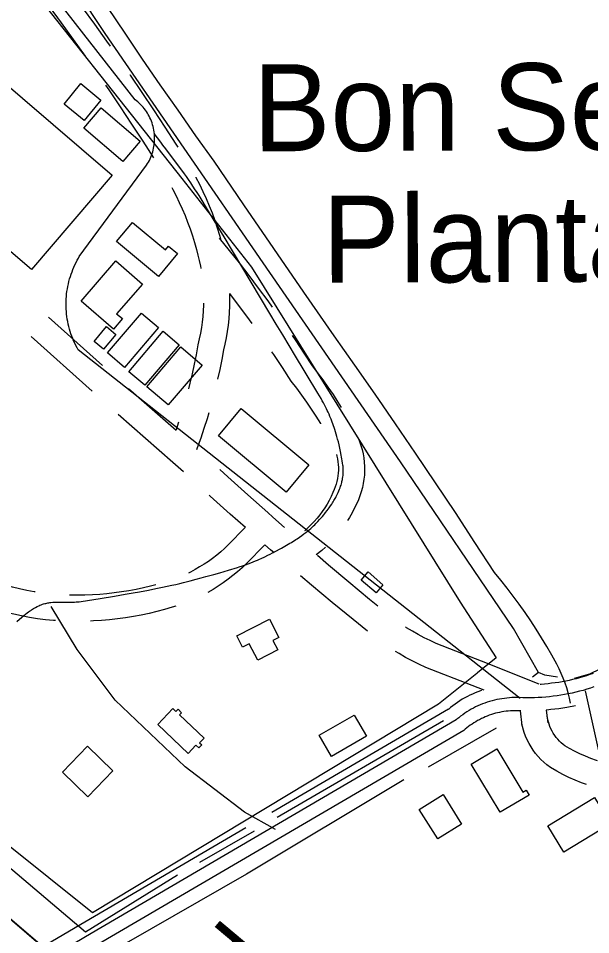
# Model space of a CAD drawing. Extents: x 3424494 to 3462436, y 522220 to 547718.
# Drawn here: x 3435143 to 3435801, y 542993 to 544046 of the extents above; entities that cross this region are included whole.
import ezdxf

# ---------------------------------------------------------------- set-up
doc = ezdxf.new("R2010")
doc.units = 0
for name, color, linetype in [('V-BLDG-IDEN', 7, 'Continuous'), ('V-BLDG-OTLN', 7, 'Continuous'), ('V-DTCH-CNTR', 7, 'Continuous'), ('V-RAIL-IDEN', 7, 'Continuous'), ('V-RAIL-TRAK', 7, 'Continuous'), ('V-ROAD-CNTR', 7, 'Continuous'), ('V-SITE-OTLN', 7, 'Continuous'), ('V-TOPO-SHOR', 7, 'Continuous')]:
    doc.layers.add(name, color=color, linetype=linetype)

msp = doc.modelspace()

# ---------------------------------------------------------------- linework, layer by layer
at = {"layer": 'V-BLDG-OTLN'}
for points in [[(3435079.4, 544012.7), (3435250.7, 543866.1), (3435157.9, 543757.6), (3434986.6, 543904.2)], [(3435195.4, 543947.7), (3435214.7, 543971.3), (3435237.8, 543952.4), (3435218.5, 543928.8)], [(3435238.1, 543943.5), (3435282.9, 543905.3), (3435262.9, 543881.8), (3435218, 543920)], [(3435273.9, 543811.8), (3435311.9, 543780.4), (3435315.4, 543784.7), (3435325.8, 543776.1), (3435304.1, 543749.8), (3435255.7, 543789.8)], [(3435254.9, 543767.5), (3435285.4, 543741), (3435255.8, 543706.9), (3435262.4, 543701.2), (3435252, 543689.2), (3435214.9, 543721.4)], [(3435245.4, 543661.8), (3435284.4, 543707.4), (3435303.8, 543690.9), (3435264.8, 543645.2)], [(3435255, 543682.9), (3435240.7, 543666), (3435230, 543675), (3435244.3, 543692)], [(3435270, 543640.1), (3435309.4, 543686.7), (3435327.7, 543671.2), (3435288.3, 543624.6)], [(3435290.4, 543623), (3435329.6, 543668.8), (3435354.2, 543647.8), (3435315, 543602)], [(3435398.9, 543598), (3435476.6, 543533.3), (3435450.5, 543501.9), (3435372.8, 543566.6)], [(3435544.8, 543410.1), (3435561.9, 543395.3), (3435554, 543386.1), (3435536.8, 543400.8)], [(3435393.9, 543336.6), (3435431.4, 543355.9), (3435442.2, 543334.9), (3435435.3, 543331.4), (3435440.9, 543320.4), (3435418, 543308.6), (3435408.3, 543327.5), (3435400.6, 543323.6)], [(3435328.2, 543245.8), (3435356.3, 543219.2), (3435351.2, 543213.8), (3435353.8, 543211.4), (3435350.4, 543207.9), (3435347, 543211.1), (3435338, 543201.6), (3435303.1, 543234.6), (3435320.5, 543253), (3435324, 543249.8), (3435326.4, 543252.3), (3435330.5, 543248.3)], [(3435542.8, 543221.3), (3435502.6, 543198), (3435488.5, 543222.3), (3435528.8, 543245.6)], [(3435193.6, 543179.8), (3435222.4, 543209.7), (3435251.5, 543181.6), (3435222.7, 543151.8)], [(3435692.9, 543206.6), (3435722.5, 543157.1), (3435726.4, 543159.4), (3435729.8, 543153.7), (3435696.5, 543133.8), (3435663.4, 543189)], [(3435631, 543154.1), (3435652.1, 543120.3), (3435624.9, 543103.3), (3435603.7, 543137.1)], [(3435751.5, 543118.3), (3435805, 543150.8), (3435823.4, 543120.6), (3435769.9, 543088)]]:
    msp.add_lwpolyline(points, close=True, dxfattribs=at)
at = {"layer": 'V-DTCH-CNTR'}
for points in [[(3435761.7, 543304.1), (3435756.1, 543314.3), (3435750.2, 543324.4), (3435744.3, 543334.3), (3435738.1, 543344.2), (3435731.7, 543353.9), (3435725.2, 543363.5), (3435718.5, 543373), (3435711.6, 543382.3), (3435704.6, 543391.6), (3435697.4, 543400.7), (3435690, 543409.6), (3435667.6, 543444.1), (3435645.1, 543478.4), (3435622.3, 543512.5), (3435599.4, 543546.6), (3435576.2, 543580.5), (3435552.9, 543614.3), (3435529.4, 543647.9), (3435505.7, 543681.5), (3435471, 543731.5), (3435436.4, 543781.7), (3435402, 543831.9), (3435367.8, 543882.3), (3435347, 543911.4), (3435326.4, 543940.7), (3435306, 543970.1), (3435285.7, 543999.5), (3435265.6, 544029.2), (3435245.7, 544058.9)], [(3435777.6, 543259.4), (3435776.3, 543265.2), (3435774.8, 543271), (3435773.1, 543276.7), (3435771.2, 543282.3), (3435769.1, 543287.9), (3435766.8, 543293.4), (3435764.3, 543298.8), (3435761.7, 543304.1)]]:
    msp.add_lwpolyline(points, dxfattribs=at)
at = {"layer": 'V-RAIL-TRAK'}
msp.add_lwpolyline([(3435190.4, 542962.1), (3435035.7, 543094.7), (3434892.9, 543218.6), (3434779.9, 543315.6), (3434627.7, 543445.6), (3434493.1, 543559.8), (3434400.9, 543640.1), (3434291.5, 543733.7), (3434167.1, 543840.9), (3434043.4, 543946.1), (3433898.6, 544070.1), (3433740.4, 544206.3), (3433526, 544390.6), (3433337.1, 544551.9)], dxfattribs=at)
at = {"layer": 'V-ROAD-CNTR'}
for p, q in [((3435352.1, 543761.8), (3435352.6, 543758.7)), ((3435239.7, 543647.2), (3435177.4, 543702.9)), ((3435227.6, 543617.8), (3435157.4, 543680.6)), ((3435721.8, 543233.5), (3435719.9, 543250.5)), ((3435751.6, 543236.8), (3435750, 543251.3))]:
    msp.add_line(p, q, dxfattribs=at)
for points in [[(3432086.3, 545626.6), (3433017.5, 544826.1), (3436584, 541768.3), (3439656.2, 539130.4), (3440791.3, 538157.4)], [(3435189.1, 544095.2), (3435202.1, 544078), (3435216.3, 544058.9), (3435230.3, 544039.6), (3435244.2, 544020.2), (3435248.2, 544014.5)], [(3435277.2, 543952.8), (3435172.7, 544086.5)], [(3435161.1, 544083), (3435163.5, 544079.3), (3435178.1, 544060.1), (3435192.1, 544041.1), (3435206, 544022.1), (3435219.7, 544002.9), (3435220.1, 544002.3)], [(3435271, 543981.7), (3435271.5, 543981), (3435284.8, 543961.3), (3435298, 543941.4), (3435311, 543921.4), (3435323.7, 543901.6), (3435326, 543898.2)], [(3435243, 543969.5), (3435246.7, 543964.1), (3435259.9, 543944.6), (3435272.9, 543924.9), (3435285.8, 543905.2), (3435298, 543886)], [(3435290.2, 543877.6), (3435291.4, 543879.4), (3435292.4, 543881.2), (3435293.4, 543883.1), (3435294.3, 543885), (3435295.2, 543886.9), (3435296, 543888.9), (3435296.7, 543890.9), (3435297.3, 543892.9), (3435297.8, 543894.9), (3435298.3, 543897), (3435298.7, 543899.1), (3435299, 543901.1), (3435299.2, 543903.2), (3435299.4, 543905.3), (3435299.4, 543907.5), (3435299.4, 543909.6), (3435299.3, 543911.7), (3435299.2, 543913.8), (3435298.9, 543915.9), (3435298.6, 543918), (3435298.2, 543920), (3435297.7, 543922.1), (3435297.1, 543924.1), (3435296.5, 543926.1), (3435295.8, 543928.1), (3435295, 543930.1), (3435294.1, 543932), (3435293.2, 543933.9), (3435292.2, 543935.7), (3435291.1, 543937.5), (3435290, 543939.3), (3435288.8, 543941), (3435287.5, 543942.7), (3435286.2, 543944.4), (3435284.8, 543945.9), (3435283.3, 543947.5), (3435281.8, 543948.9), (3435280.2, 543950.3), (3435278.6, 543951.7), (3435277.2, 543952.8)], [(3435306.5, 543904), (3435302.8, 543909), (3435299.1, 543914.1)], [(3435503.9, 543489.4), (3435504.7, 543490.8), (3435505.5, 543492.1), (3435506.3, 543493.4), (3435507, 543494.6), (3435507.6, 543495.8), (3435508.2, 543496.9), (3435509.4, 543499.2), (3435510.4, 543501.3), (3435511.2, 543503.3), (3435512, 543505.1), (3435512.7, 543506.9), (3435513.2, 543508.5), (3435513.7, 543510), (3435514.1, 543511.5), (3435514.5, 543512.8), (3435514.8, 543514.1), (3435515.1, 543515.3), (3435515.3, 543516.4), (3435515.5, 543517.4), (3435515.8, 543519.4), (3435516, 543521.1), (3435516.1, 543522.6), (3435516.2, 543523.9), (3435516.3, 543525), (3435516.3, 543526), (3435516.3, 543527.7), (3435516.2, 543529), (3435516.2, 543530), (3435516, 543531.5), (3435515.8, 543532.9), (3435515.5, 543535.3), (3435515.1, 543537.7), (3435514.8, 543539.9), (3435514.4, 543542.1), (3435514, 543544.3), (3435513.2, 543548.5), (3435512.4, 543552.4), (3435511.5, 543556.1), (3435510.7, 543559.5), (3435509.8, 543562.8), (3435509, 543565.8), (3435508.2, 543568.6), (3435507.4, 543571.3), (3435506.6, 543573.7), (3435505.8, 543576.1), (3435505.1, 543578.2), (3435504.3, 543580.3), (3435503.6, 543582.2), (3435502.3, 543585.7), (3435501, 543588.7), (3435499.9, 543591.4), (3435498.8, 543593.7), (3435497.9, 543595.7), (3435497.1, 543597.5), (3435495.6, 543600.5), (3435494.4, 543602.8), (3435493.5, 543604.4), (3435492.1, 543606.9), (3435490.7, 543609.4), (3435487, 543615.6), (3435483.6, 543621.4), (3435477.1, 543632.2), (3435471.5, 543641.6), (3435461.5, 543658), (3435446.7, 543682.5), (3435439.2, 543694.8), (3435431.9, 543707.2), (3435410.4, 543743.2), (3435388.9, 543779.2), (3435379.4, 543795.1), (3435372.2, 543807), (3435361.4, 543824.8), (3435350.5, 543842.6), (3435349.1, 543844.9), (3435347.6, 543847.2), (3435346.2, 543849.4), (3435343.5, 543853.6), (3435340.9, 543857.4), (3435338.4, 543861), (3435336, 543864.4), (3435333.7, 543867.5), (3435329.4, 543873.4), (3435325.7, 543878.5), (3435312.3, 543896.2), (3435308.9, 543900.7), (3435306.5, 543904)], [(3435212.9, 543772.5), (3435290.2, 543877.6)], [(3435346.7, 543864), (3435346.9, 543863.6), (3435351, 543855.6), (3435355, 543847.5), (3435358.7, 543839.3), (3435362.2, 543831), (3435365.5, 543822.7), (3435368.6, 543814.2), (3435371.4, 543805.7), (3435374.1, 543797.1), (3435375.7, 543791.6)], [(3435319.1, 543852), (3435320.4, 543849.5), (3435324.2, 543842.2), (3435327.8, 543834.8), (3435331.2, 543827.3), (3435334.4, 543819.7), (3435337.4, 543812), (3435340.3, 543804.3), (3435342.9, 543796.5), (3435345.3, 543788.6), (3435347.6, 543780.6), (3435349.3, 543774.2), (3435350.8, 543767.9), (3435352.2, 543761.4)], [(3435373.8, 543793.9), (3435385.2, 543779.6), (3435396.5, 543765.3), (3435407.6, 543750.8), (3435418.6, 543736.3), (3435429.4, 543721.6), (3435434.5, 543714.5)], [(3435211.7, 543665.2), (3435210.3, 543667.7), (3435208.9, 543670.3), (3435207.6, 543672.9), (3435206.4, 543675.6), (3435205.3, 543678.3), (3435204.3, 543681), (3435203.3, 543683.7), (3435202.4, 543686.5), (3435201.6, 543689.3), (3435200.8, 543692.1), (3435200.2, 543695), (3435199.6, 543697.8), (3435199.1, 543700.7), (3435198.6, 543703.6), (3435198.3, 543706.5), (3435198, 543709.4), (3435197.8, 543712.3), (3435197.7, 543715.2), (3435197.7, 543718.1), (3435197.7, 543721), (3435197.9, 543723.9), (3435198.1, 543726.8), (3435198.3, 543729.7), (3435198.7, 543732.6), (3435199.2, 543735.5), (3435199.7, 543738.3), (3435200.3, 543741.2), (3435201, 543744), (3435201.7, 543746.8), (3435202.6, 543749.6), (3435203.5, 543752.4), (3435204.5, 543755.1), (3435205.5, 543757.8), (3435206.7, 543760.5), (3435207.9, 543763.2), (3435209.1, 543765.8), (3435210.5, 543768.4), (3435211.9, 543770.9), (3435212.9, 543772.5)], [(3435385.6, 543730.2), (3435385.7, 543723.1), (3435385.6, 543715.7), (3435385.3, 543708.3), (3435384.7, 543700.9), (3435383.9, 543693.6), (3435382.9, 543686.3), (3435381.6, 543679), (3435380.1, 543671.7), (3435378.5, 543665.2), (3435376.6, 543654.2), (3435374.3, 543642.7), (3435371.8, 543631.5)], [(3435385.6, 543730.2), (3435394.5, 543718.4), (3435405.1, 543704), (3435411, 543695.8)], [(3435355.7, 543718.9), (3435355.6, 543716.6), (3435355.3, 543710.2), (3435354.8, 543703.7), (3435354.1, 543697.3), (3435353.2, 543690.9), (3435352.1, 543684.6), (3435350.8, 543678.2), (3435349.2, 543671.3), (3435347.1, 543659.8), (3435344.9, 543648.8), (3435342.5, 543637.9), (3435340, 543627.1), (3435338.3, 543620.6)], [(3435457.4, 543681.7), (3435460.8, 543676.8), (3435470.9, 543661.7), (3435480.5, 543647), (3435486.4, 543639.4), (3435492.6, 543631), (3435498.6, 543622.5), (3435504.5, 543613.9), (3435510.1, 543605.2), (3435513.9, 543599.2)], [(3435719.7, 543264.8), (3435211.7, 543665.2)], [(3435433.9, 543663), (3435435.9, 543660), (3435445.9, 543645.1), (3435456, 543629.5), (3435462.5, 543621.2), (3435468.3, 543613.4), (3435474, 543605.4), (3435479.5, 543597.3), (3435484.8, 543589.1), (3435490, 543580.8), (3435490.2, 543580.4)], [(3435324.1, 543572.7), (3435272, 543618.4), (3435269.6, 543620.6)], [(3435332.6, 543525.3), (3435320.5, 543535.9), (3435257.5, 543591.2)], [(3435361.7, 543592.8), (3435359.7, 543586), (3435356.2, 543574.9), (3435352.5, 543563.8), (3435348.5, 543552.7), (3435347.7, 543550.6)], [(3435327, 543582.2), (3435324.1, 543573.6), (3435323.9, 543572.9)], [(3435533.3, 543564.3), (3435535, 543560), (3435536.6, 543555.4), (3435537.9, 543550.7), (3435539, 543545.9), (3435539.8, 543541.1), (3435540.4, 543536.2), (3435540.7, 543531.3), (3435540.7, 543526.4), (3435540.5, 543521.5), (3435540, 543516.6), (3435539.2, 543511.8), (3435538.2, 543507), (3435536.9, 543502.3), (3435535.4, 543497.6), (3435533.6, 543493.1), (3435531.7, 543488.9), (3435529.2, 543483.6), (3435526.4, 543478.1), (3435523.4, 543472.7), (3435521.3, 543469.3)], [(3435508.4, 543544.9), (3435508.8, 543543.3), (3435509.6, 543540.1), (3435510.1, 543536.8), (3435510.5, 543533.6), (3435510.7, 543530.3), (3435510.7, 543527), (3435510.6, 543523.8), (3435510.2, 543520.5), (3435509.7, 543517.3), (3435509, 543514.1), (3435508.2, 543510.9), (3435507.1, 543507.8), (3435505.9, 543504.8), (3435504.4, 543501.4), (3435502.2, 543496.7), (3435500, 543492.3), (3435497.6, 543488), (3435495, 543483.8), (3435492.2, 543479.7), (3435489.3, 543475.7), (3435486.2, 543471.8), (3435482.9, 543468.1), (3435479.5, 543464.5), (3435476, 543461), (3435472.5, 543457.9), (3435471.8, 543457.3)], [(3435448.9, 543461.2), (3435435.3, 543473.1), (3435429.4, 543478.4), (3435406.4, 543498.8), (3435383.6, 543519.5), (3435374.5, 543527.9)], [(3435403.8, 543461), (3435386.4, 543476.5), (3435363.4, 543497.3), (3435362.3, 543498.4)], [(3435179.1, 543374.8), (3435180.2, 543375), (3435182.3, 543375.2), (3435184.3, 543375.3), (3435186.2, 543375.4), (3435188, 543375.4), (3435191.4, 543375.4), (3435197.3, 543375.4), (3435201.7, 543375.3), (3435205, 543375.4), (3435207.5, 543375.4), (3435209.4, 543375.6), (3435210.8, 543375.7), (3435212.8, 543375.9), (3435214.9, 543376.2), (3435236.8, 543379.7), (3435253.3, 543382.4), (3435265.7, 543384.5), (3435274.9, 543386.1), (3435281.9, 543387.4), (3435292.3, 543389.3), (3435297.5, 543390.3), (3435302.7, 543391.3), (3435308.5, 543392.5), (3435314, 543393.6), (3435319.1, 543394.8), (3435323.9, 543395.8), (3435328.3, 543396.9), (3435332.5, 543397.9), (3435340.3, 543399.9), (3435347.2, 543401.6), (3435353.1, 543403.2), (3435358.3, 543404.7), (3435367.5, 543407.2), (3435374.3, 543409.2), (3435384.5, 543412.2), (3435394.8, 543415.3), (3435396.7, 543415.9), (3435400.4, 543417.1), (3435403.8, 543418.3), (3435407, 543419.4), (3435410, 543420.6), (3435412.8, 543421.7), (3435415.3, 543422.7), (3435417.7, 543423.8), (3435420, 543424.8), (3435422.1, 543425.7), (3435426, 543427.5), (3435429.4, 543429.2), (3435432.4, 543430.7), (3435435, 543432), (3435439.5, 543434.4), (3435442.9, 543436.2), (3435445.4, 543437.6), (3435449.3, 543439.8), (3435453.1, 543442), (3435455, 543443.1), (3435456.7, 543444.1), (3435458.5, 543445.2), (3435460.1, 543446.2), (3435461.7, 543447.2), (3435463.2, 543448.2), (3435466, 543450.1), (3435468.6, 543451.9), (3435471, 543453.7), (3435473.3, 543455.4), (3435475.3, 543457.1), (3435477.2, 543458.6), (3435478.9, 543460.2), (3435480.6, 543461.6), (3435482.1, 543463), (3435483.5, 543464.3), (3435484.7, 543465.6), (3435485.9, 543466.8), (3435487.1, 543468), (3435489.1, 543470.2), (3435490.9, 543472.2), (3435492.5, 543474), (3435493.8, 543475.6), (3435495, 543477.1), (3435496, 543478.3), (3435497.8, 543480.7), (3435499.1, 543482.4), (3435500.1, 543483.8), (3435501.5, 543485.9), (3435503, 543488.1), (3435503.9, 543489.4)], [(3435403.7, 543461.1), (3435384.1, 543441.2), (3435379.8, 543437.1), (3435375.4, 543433.2), (3435370.8, 543429.4), (3435366.1, 543425.7), (3435361.2, 543422.2), (3435356.3, 543418.9), (3435351.2, 543415.8), (3435346, 543412.8), (3435340.8, 543410), (3435338.3, 543408.8)], [(3435426.2, 543441.2), (3435405.2, 543419.8), (3435400.1, 543415), (3435394.9, 543410.4), (3435389.5, 543405.9), (3435384, 543401.7), (3435378.3, 543397.6), (3435372.5, 543393.7), (3435366.6, 543390), (3435360.6, 543386.6)], [(3435436.9, 543431.9), (3435432.8, 543435.4), (3435426.1, 543441.3)], [(3435495.8, 543438.6), (3435491.7, 543434.8), (3435485.3, 543429.8)], [(3435555.9, 543370.9), (3435546.5, 543378.6), (3435522.8, 543398.2), (3435499.2, 543418), (3435486.5, 543428.8)], [(3435162, 543387.1), (3435160.9, 543387.3), (3435152.6, 543388.9), (3435144.3, 543390.7), (3435136.1, 543392.7), (3435127.9, 543394.9), (3435119.8, 543397.3), (3435111.8, 543399.8), (3435103.8, 543402.6), (3435095.8, 543405.5), (3435088, 543408.6), (3435080.2, 543411.9), (3435072.5, 543415.4), (3435067.2, 543418)], [(3435544.1, 543341.9), (3435527.5, 543355.4), (3435503.6, 543375.1), (3435479.8, 543395), (3435467.2, 543405.8)], [(3435300.8, 543395.3), (3435294.7, 543393.7), (3435286.5, 543391.7), (3435278.2, 543390), (3435269.9, 543388.4), (3435261.5, 543387.1), (3435253.1, 543386), (3435244.7, 543385), (3435236.3, 543384.3), (3435227.9, 543383.8), (3435219.4, 543383.5), (3435211, 543383.4), (3435202.5, 543383.5), (3435201.8, 543383.5)], [(3435185.7, 543354.3), (3435183.4, 543354.4), (3435174.2, 543355.2), (3435164.8, 543356.3), (3435155.6, 543357.8), (3435146.6, 543359.5), (3435137.6, 543361.5), (3435128.7, 543363.6), (3435119.9, 543366), (3435111.1, 543368.6), (3435102.3, 543371.3), (3435093.7, 543374.3), (3435088.5, 543376.2)], [(3435140.9, 543353.3), (3435146.9, 543358.2), (3435149.1, 543360), (3435151.1, 543361.6), (3435152.9, 543363), (3435154.4, 543364.1), (3435155.8, 543365.1), (3435157.1, 543365.9), (3435158.1, 543366.7), (3435160.1, 543367.9), (3435161.6, 543368.8), (3435162.7, 543369.4), (3435164.5, 543370.3), (3435166.2, 543371.2), (3435167.7, 543371.9), (3435169.1, 543372.4), (3435170.4, 543372.9), (3435171.8, 543373.3), (3435173.1, 543373.7), (3435174.3, 543374), (3435175.6, 543374.3), (3435176.8, 543374.5), (3435177.9, 543374.7), (3435179.1, 543374.8)], [(3435438.5, 543114), (3435402.8, 543134.1), (3435334.6, 543186.2), (3435254.2, 543262.6), (3435210.6, 543320.9), (3435180.6, 543370.5)], [(3435323.9, 543370.8), (3435319.7, 543369.5), (3435310.9, 543366.9), (3435302, 543364.6), (3435293, 543362.4), (3435284, 543360.5), (3435275, 543358.9), (3435265.9, 543357.4), (3435256.8, 543356.2), (3435247.7, 543355.2), (3435238.5, 543354.4), (3435229.3, 543353.8), (3435225.7, 543353.7)], [(3435741.6, 543281.2), (3435675.3, 543307.5), (3435623, 543328), (3435616.1, 543331.1), (3435609.2, 543334.5), (3435602.4, 543338.2), (3435595.7, 543342), (3435589.1, 543346), (3435587.8, 543346.9)], [(3435678.1, 543274.1), (3435664.3, 543279.6), (3435611.3, 543300.3), (3435603.3, 543304), (3435595.5, 543307.8), (3435587.9, 543311.9), (3435580.4, 543316.2), (3435576.5, 543318.5)], [(3435803.5, 543293.4), (3435799.6, 543292.1), (3435795.7, 543290.8), (3435791.8, 543289.6), (3435787.9, 543288.5), (3435783.9, 543287.4), (3435779.9, 543286.4), (3435776, 543285.5), (3435771.9, 543284.7), (3435767.9, 543283.9), (3435763.9, 543283.2), (3435759.8, 543282.6), (3435755.8, 543282.1), (3435751.7, 543281.6), (3435747.6, 543281.2), (3435743.6, 543280.9), (3435742.6, 543280.8)], [(3435675, 543273.9), (3435674, 543273.6), (3435670.9, 543272.4), (3435667.8, 543271.1), (3435664.8, 543269.8), (3435661.8, 543268.4), (3435658.9, 543266.9), (3435656, 543265.3), (3435653.1, 543263.7), (3435650.3, 543261.9), (3435647.5, 543260.1), (3435644.8, 543258.2), (3435642.2, 543256.2), (3435639.6, 543254.2), (3435637.1, 543252.1), (3435637.1, 543252.2)], [(3435804.4, 543277.9), (3435800.3, 543276.5), (3435796.1, 543275.2), (3435791.9, 543274), (3435787.7, 543272.9), (3435783.4, 543271.9), (3435779.2, 543270.9), (3435774.9, 543270), (3435770.6, 543269.2), (3435766.3, 543268.4), (3435762, 543267.8), (3435757.6, 543267.2), (3435753.3, 543266.7), (3435749, 543266.3), (3435744.6, 543265.9), (3435740.2, 543265.7), (3435735.9, 543265.5), (3435731.5, 543265.4), (3435727.1, 543265.4), (3435722.8, 543265.4), (3435718.8, 543265.6)], [(3437310.2, 542319.9), (3436715.7, 543202.9), (3436703.6, 543212.4), (3436689.4, 543216.7), (3436671.7, 543213.3), (3436648.2, 543201.1), (3436093.1, 542861.6), (3436083.9, 542856.7), (3436073.4, 542853.7), (3436051, 542854.7), (3436027.3, 542871.4), (3435835.4, 543140.8), (3435823.1, 543161.6), (3435812.9, 543190.5), (3435794.8, 543273.5)], [(3435718.8, 543265.6), (3435715.9, 543265.6), (3435713, 543265.6), (3435710.1, 543265.6), (3435707.2, 543265.4), (3435704.4, 543265.1), (3435701.5, 543264.8), (3435698.6, 543264.4), (3435695.8, 543264), (3435692.9, 543263.4), (3435690.1, 543262.8), (3435687.3, 543262), (3435684.5, 543261.3), (3435681.8, 543260.4), (3435679.1, 543259.4), (3435676.4, 543258.4), (3435673.7, 543257.3), (3435671, 543256.2), (3435668.4, 543254.9), (3435665.8, 543253.6), (3435663.3, 543252.2), (3435660.8, 543250.8), (3435658.4, 543249.3), (3435655.9, 543247.7), (3435653.6, 543246), (3435651.2, 543244.3), (3435649, 543242.5), (3435646.7, 543240.7), (3435645.9, 543240)], [(3435637.1, 543252.2), (3435434.3, 543133.6)], [(3435783.2, 543256.3), (3435773.3, 543254.4), (3435768.7, 543253.6), (3435764.1, 543252.9), (3435759.5, 543252.3), (3435754.9, 543251.8), (3435750.3, 543251.3), (3435749.5, 543251.3)], [(3435718.4, 543250.6), (3435715.7, 543250.6), (3435713.2, 543250.6), (3435710.7, 543250.6), (3435708.3, 543250.4), (3435705.8, 543250.2), (3435703.4, 543249.9), (3435700.9, 543249.6), (3435698.5, 543249.2), (3435696, 543248.7), (3435693.6, 543248.2), (3435691.2, 543247.6), (3435688.8, 543246.9), (3435686.5, 543246.1), (3435684.1, 543245.3), (3435681.8, 543244.5), (3435679.5, 543243.5), (3435677.3, 543242.5), (3435675, 543241.5), (3435672.8, 543240.3), (3435670.7, 543239.2), (3435668.5, 543237.9), (3435666.4, 543236.6), (3435664.4, 543235.3), (3435662.3, 543233.8), (3435660.3, 543232.4), (3435658.4, 543230.8), (3435656.4, 543229.2), (3435654.7, 543227.7)], [(3435720.4, 543250.5), (3435718.3, 543250.6)], [(3435808.5, 543193), (3435807.2, 543193.4), (3435800.9, 543195.8), (3435794.5, 543198.3), (3435788.3, 543201.1), (3435782.2, 543204.1), (3435776.2, 543207.3), (3435770.9, 543210.3), (3435769.1, 543211.7), (3435766.9, 543213.6), (3435764.8, 543215.6), (3435762.8, 543217.7), (3435761, 543219.9), (3435759.3, 543222.2), (3435757.7, 543224.7), (3435756.2, 543227.2), (3435755, 543229.8), (3435753.8, 543232.4), (3435752.8, 543235.1), (3435752, 543237.9), (3435751.3, 543240.7), (3435750.7, 543244)], [(3435645.9, 543240), (3435226.7, 542994.7), (3434699.7, 542682.6), (3433265.6, 541846), (3431743, 540947.2), (3429942, 539889.8), (3428572.6, 539081)], [(3435795.7, 543165.7), (3435790, 543167.8), (3435782.8, 543170.7), (3435775.7, 543173.9), (3435768.6, 543177.3), (3435761.7, 543181), (3435754.3, 543185.2), (3435750.2, 543188.3), (3435746.7, 543191.3), (3435743.4, 543194.5), (3435740.2, 543197.9), (3435737.3, 543201.4), (3435734.6, 543205.2), (3435732.1, 543209), (3435729.8, 543213), (3435727.7, 543217.1), (3435725.9, 543221.4), (3435724.3, 543225.7), (3435721.5, 543235.2)], [(3435654.7, 543227.7), (3435234.3, 542981.8), (3435158.4, 542936.8)], [(3435404.4, 543116), (3435219.1, 543007.7), (3435143.1, 542962.6)]]:
    msp.add_lwpolyline(points, dxfattribs=at)
at = {"layer": 'V-SITE-OTLN'}
msp.add_lwpolyline([(3435054, 544212.5), (3435122.7, 544125.5), (3435330.7, 543862.1), (3435410.9, 543760.5), (3435650.8, 543375.2), (3435692, 543311.4), (3435670.6, 543294.1), (3435669.8, 543293.5), (3435625.7, 543258), (3435228.1, 543018.1), (3434770.3, 543384.9), (3434159, 543894.8), (3434445.3, 543990.3), (3434450.2, 543991.9)], close=True, dxfattribs=at)
at = {"layer": 'V-TOPO-SHOR'}
for p, q in [((3435631.6, 543239), (3435440.4, 543127.9)), ((3435691.9, 543230.6), (3435613.7, 543185.8)), ((3435414, 543112.3), (3435351, 543076.2)), ((3435325.8, 543061.5), (3435220, 542996.2))]:
    msp.add_line(p, q, dxfattribs=at)
for points in [[(3435740.6, 543294.4), (3435712, 543345.2), (3435582, 543536.8), (3435424.3, 543765.3), (3435242.7, 544029), (3435179.7, 544123.8)], [(3436402.6, 543640.5), (3436053.1, 543438.7), (3435895.2, 543346.2), (3435822.2, 543303.8), (3435799.4, 543292.6), (3435781.8, 543287.5)], [(3435220, 542996.2), (3434958.7, 543217.4), (3434841.9, 543316.2), (3434823.5, 543299.3)], [(3435762.7, 543289.2), (3435747.8, 543291.3), (3435740.6, 543294.4), (3435733.8, 543289.3)], [(3435585.9, 543171.2), (3435404.9, 543062.9), (3435266.8, 542983.5), (3435245.3, 542970.2)]]:
    msp.add_lwpolyline(points, dxfattribs=at)

# ---------------------------------------------------------------- texts
at = {"layer": 'V-BLDG-IDEN'}
for s, p in [('Bon Secours', (3435412.5, 543893.5)), ('Plantation', (3435492.2, 543742.4))]:
    msp.add_text(s, height=100, rotation=0.2224, dxfattribs=at).set_placement(p)
at = {"layer": 'V-RAIL-IDEN'}
msp.add_text('TEXAS', height=83, rotation=319.9824, dxfattribs=at).set_placement((3435319.2, 542947.2))

doc.saveas('drawing.dxf')
